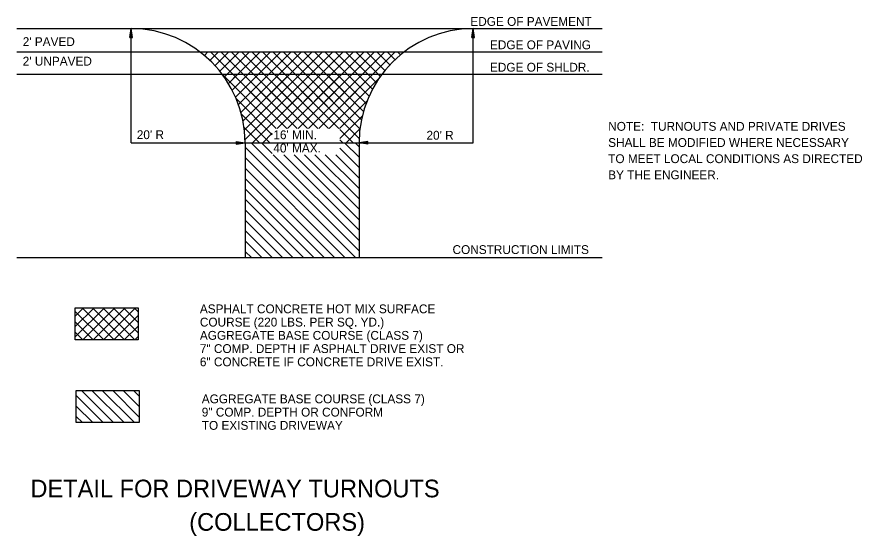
# Model space of a CAD drawing. Extents: x 836 to 5683, y -463 to 1545.
# Drawn here: x 2195 to 2769, y 147 to 499 of the extents above; entities that cross this region are included whole.
import ezdxf

# ---------------------------------------------------------------- set-up
doc = ezdxf.new("R2010")
doc.units = 0
for name, color, linetype in [('Default', 7, 'Continuous'), ('G-ANNO-NPLT', 7, 'Continuous'), ('R_Grid', 7, 'Continuous')]:
    doc.layers.add(name, color=color, linetype=linetype)

msp = doc.modelspace()

# ---------------------------------------------------------------- linework, layer by layer
at = {"layer": 'G-ANNO-NPLT'}
for p, q in [((2194.89, 491.49), (2592.63, 491.49)), ((2272.5, 414), (2272.5, 491.49)), ((2504.95, 414), (2504.95, 491.49)), ((2194.89, 475.72), (2592.63, 475.72)), ((2322.37, 473.31), (2324.78, 475.72)), ((2326.1, 469.96), (2331.85, 475.72)), ((2378.31, 423.79), (2326.38, 475.72)), ((2329.6, 466.39), (2338.92, 475.72)), ((2332.86, 462.59), (2345.99, 475.72)), ((2385.38, 423.79), (2333.45, 475.72)), ((2335.87, 458.52), (2353.06, 475.72)), ((2338.66, 454.25), (2360.14, 475.72)), ((2392.45, 423.79), (2340.52, 475.72)), ((2341.22, 449.73), (2367.21, 475.72)), ((2343.5, 444.94), (2374.28, 475.72)), ((2345.5, 439.87), (2381.35, 475.72)), ((2347.19, 434.49), (2388.42, 475.72)), ((2399.52, 423.79), (2347.59, 475.72)), ((2348.53, 428.75), (2395.49, 475.72)), ((2349.46, 422.61), (2402.56, 475.72)), ((2349.92, 416), (2409.63, 475.72)), ((2406.59, 423.79), (2354.66, 475.72)), ((2354.99, 414), (2416.7, 475.72)), ((2413.66, 423.79), (2361.74, 475.72)), ((2427.58, 416.95), (2368.81, 475.72)), ((2371.85, 423.79), (2423.77, 475.72)), ((2428.1, 423.5), (2375.88, 475.72)), ((2378.92, 423.79), (2430.85, 475.72)), ((2429.08, 429.58), (2382.95, 475.72)), ((2385.99, 423.79), (2437.92, 475.72)), ((2430.47, 435.27), (2390.02, 475.72)), ((2393.06, 423.79), (2444.99, 475.72)), ((2432.2, 440.6), (2397.09, 475.72)), ((2400.13, 423.79), (2452.06, 475.72)), ((2434.25, 445.63), (2404.16, 475.72)), ((2436.57, 450.38), (2411.23, 475.72)), ((2439.16, 454.86), (2418.3, 475.72)), ((2441.99, 459.1), (2425.37, 475.72)), ((2445.03, 463.13), (2432.45, 475.72)), ((2448.33, 466.9), (2439.52, 475.72)), ((2451.86, 470.44), (2446.59, 475.72)), ((2455.62, 473.75), (2453.66, 475.72)), ((2194.89, 460.5), (2592.63, 460.5)), ((2371.23, 423.79), (2334.37, 460.66)), ((2371.23, 423.79), (2334.53, 460.5)), ((2335.87, 458.52), (2337.84, 460.5)), ((2338.66, 454.25), (2344.91, 460.5)), ((2341.22, 449.73), (2351.99, 460.5)), ((2378.31, 423.79), (2341.6, 460.5)), ((2343.5, 444.94), (2359.06, 460.5)), ((2345.5, 439.87), (2366.13, 460.5)), ((2347.19, 434.49), (2373.2, 460.5)), ((2348.53, 428.75), (2380.27, 460.5)), ((2385.38, 423.79), (2348.67, 460.5)), ((2349.46, 422.61), (2387.34, 460.5)), ((2349.92, 416), (2394.41, 460.5)), ((2354.99, 414), (2401.48, 460.5)), ((2392.45, 423.79), (2355.74, 460.5)), ((2399.52, 423.79), (2362.81, 460.5)), ((2406.59, 423.79), (2369.88, 460.5)), ((2371.85, 423.79), (2408.55, 460.5)), ((2413.66, 423.79), (2376.96, 460.5)), ((2378.92, 423.79), (2415.62, 460.5)), ((2427.58, 416.95), (2384.03, 460.5)), ((2385.99, 423.79), (2422.7, 460.5)), ((2428.1, 423.5), (2391.1, 460.5)), ((2393.06, 423.79), (2429.77, 460.5)), ((2429.08, 429.58), (2398.17, 460.5)), ((2400.13, 423.79), (2436.84, 460.5)), ((2430.47, 435.27), (2405.24, 460.5)), ((2432.2, 440.6), (2412.31, 460.5)), ((2434.25, 445.63), (2419.38, 460.5)), ((2436.57, 450.38), (2426.45, 460.5)), ((2439.16, 454.86), (2433.52, 460.5)), ((2441.99, 459.1), (2440.6, 460.5)), ((2407.2, 423.79), (2440.79, 457.38)), ((2407.2, 423.79), (2440.79, 457.38)), ((2368.5, 419.45), (2343.85, 444.1)), ((2368.5, 419.45), (2343.85, 444.1)), ((2414.27, 423.79), (2432.91, 442.42)), ((2414.27, 423.79), (2432.91, 442.42)), ((2366.88, 414), (2347.46, 433.42)), ((2366.88, 414), (2347.46, 433.42)), ((2414.35, 416.8), (2429.65, 432.1)), ((2414.35, 416.8), (2429.65, 432.1)), ((2359.81, 414), (2349.25, 424.56)), ((2359.81, 414), (2349.25, 424.56)), ((2362.06, 414), (2368.5, 420.44)), ((2362.06, 414), (2368.5, 420.44)), ((2423.45, 414), (2414.35, 423.1)), ((2423.45, 414), (2414.35, 423.1)), ((2418.63, 414), (2428.09, 423.47)), ((2418.63, 414), (2428.09, 423.47)), ((2272.5, 414), (2349.99, 414)), ((2349.99, 414), (2349.99, 336.01)), ((2349.99, 414), (2427.47, 414)), ((2427.47, 340.56), (2354.03, 414)), ((2368.5, 406.61), (2361.1, 414)), ((2368.5, 413.68), (2368.17, 414)), ((2368.5, 413.68), (2368.17, 414)), ((2416.38, 414), (2414.35, 416.03)), ((2416.38, 414), (2414.35, 416.03)), ((2427.47, 404.2), (2417.67, 414)), ((2427.47, 411.28), (2424.74, 414)), ((2427.47, 411.28), (2424.74, 414)), ((2427.47, 414), (2427.47, 336.01)), ((2427.47, 414), (2504.95, 414)), ((2424.96, 336.01), (2349.99, 410.98)), ((2427.47, 397.13), (2414.35, 410.25)), ((2417.89, 336.01), (2349.99, 403.91)), ((2427.47, 347.64), (2369.18, 405.92)), ((2427.47, 354.71), (2376.25, 405.92)), ((2427.47, 361.78), (2383.33, 405.92)), ((2427.47, 368.85), (2390.4, 405.92)), ((2427.47, 375.92), (2397.47, 405.92)), ((2427.47, 382.99), (2404.54, 405.92)), ((2427.47, 390.06), (2411.61, 405.92)), ((2410.82, 336.01), (2349.99, 396.84)), ((2403.75, 336.01), (2349.99, 389.76)), ((2396.67, 336.01), (2349.99, 382.69)), ((2389.6, 336.01), (2349.99, 375.62)), ((2382.53, 336.01), (2349.99, 368.55)), ((2375.46, 336.01), (2349.99, 361.48)), ((2368.39, 336.01), (2349.99, 354.41)), ((2361.32, 336.01), (2349.99, 347.34)), ((2354.25, 336.01), (2349.99, 340.27)), ((2194.89, 336.01), (2592.63, 336.01)), ((2234.54, 296.26), (2240.23, 301.95)), ((2234.54, 289.19), (2247.3, 301.95)), ((2234.54, 282.12), (2254.37, 301.95)), ((2253.9, 280.13), (2234.54, 299.5)), ((2260.97, 280.13), (2239.15, 301.95)), ((2239.62, 280.13), (2261.44, 301.95)), ((2268.04, 280.13), (2246.22, 301.95)), ((2246.69, 280.13), (2268.51, 301.95)), ((2275.11, 280.13), (2253.29, 301.95)), ((2253.76, 280.13), (2275.59, 301.95)), ((2277.35, 284.97), (2260.36, 301.95)), ((2277.35, 292.04), (2267.43, 301.95)), ((2277.35, 299.11), (2274.5, 301.95)), ((2260.84, 280.13), (2277.35, 296.64)), ((2246.83, 280.13), (2234.54, 292.42)), ((2267.91, 280.13), (2277.35, 289.57)), ((2239.76, 280.13), (2234.54, 285.35)), ((2274.98, 280.13), (2277.35, 282.5)), ((2253.57, 223.98), (2235.22, 242.33)), ((2260.64, 223.98), (2238.82, 245.8)), ((2267.71, 223.98), (2245.89, 245.8)), ((2274.78, 223.98), (2252.96, 245.8)), ((2278.03, 227.8), (2260.03, 245.8)), ((2278.03, 234.87), (2267.11, 245.8)), ((2278.03, 241.94), (2274.18, 245.8)), ((2246.5, 223.98), (2235.22, 235.25)), ((2239.43, 223.98), (2235.22, 228.18))]:
    msp.add_line(p, q, dxfattribs=at)
for points in [[(2234.54, 301.95), (2277.35, 301.95), (2277.35, 280.13), (2234.54, 280.13)], [(2235.22, 245.8), (2278.03, 245.8), (2278.03, 223.98), (2235.22, 223.98)]]:
    msp.add_lwpolyline(points, close=True, dxfattribs=at)
for centre, start, end in [((2272.5, 414), 0, 90), ((2504.95, 414), 90, 180)]:
    msp.add_arc(centre, 77.48, start, end, dxfattribs=at)
at = {"layer": 'R_Grid'}
for p, q in [((2271.6, 485.49), (2272.5, 491.49)), ((2271.6, 485.49), (2272.5, 491.49)), ((2271.75, 485.49), (2272.5, 490.49)), ((2271.75, 485.49), (2272.5, 490.49)), ((2271.91, 485.49), (2272.5, 489.45)), ((2271.91, 485.49), (2272.5, 489.45)), ((2272.06, 485.49), (2272.5, 488.46)), ((2272.06, 485.49), (2272.5, 488.46)), ((2273.4, 485.49), (2272.5, 491.49)), ((2273.4, 485.49), (2272.5, 491.49)), ((2273.25, 485.49), (2272.5, 490.49)), ((2273.25, 485.49), (2272.5, 490.49)), ((2273.1, 485.49), (2272.5, 489.45)), ((2273.1, 485.49), (2272.5, 489.45)), ((2272.95, 485.49), (2272.5, 488.46)), ((2272.95, 485.49), (2272.5, 488.46)), ((2504.05, 485.49), (2504.95, 491.49)), ((2504.05, 485.49), (2504.95, 491.49)), ((2504.2, 485.49), (2504.95, 490.49)), ((2504.2, 485.49), (2504.95, 490.49)), ((2504.36, 485.49), (2504.95, 489.45)), ((2504.36, 485.49), (2504.95, 489.45)), ((2504.51, 485.49), (2504.95, 488.46)), ((2504.51, 485.49), (2504.95, 488.46)), ((2505.85, 485.49), (2504.95, 491.49)), ((2505.85, 485.49), (2504.95, 491.49)), ((2505.7, 485.49), (2504.95, 490.49)), ((2505.7, 485.49), (2504.95, 490.49)), ((2505.55, 485.49), (2504.95, 489.45)), ((2505.55, 485.49), (2504.95, 489.45)), ((2505.4, 485.49), (2504.95, 488.46)), ((2505.4, 485.49), (2504.95, 488.46)), ((2271.6, 485.49), (2273.4, 485.49)), ((2271.6, 485.49), (2273.4, 485.49)), ((2272.21, 485.49), (2272.5, 487.44)), ((2272.21, 485.49), (2272.5, 487.44)), ((2272.36, 485.49), (2272.5, 486.44)), ((2272.36, 485.49), (2272.5, 486.44)), ((2272.8, 485.49), (2272.5, 487.44)), ((2272.8, 485.49), (2272.5, 487.44)), ((2272.64, 485.49), (2272.5, 486.44)), ((2272.64, 485.49), (2272.5, 486.44)), ((2504.05, 485.49), (2505.85, 485.49)), ((2504.05, 485.49), (2505.85, 485.49)), ((2504.66, 485.49), (2504.95, 487.44)), ((2504.66, 485.49), (2504.95, 487.44)), ((2504.81, 485.49), (2504.95, 486.44)), ((2504.81, 485.49), (2504.95, 486.44)), ((2505.25, 485.49), (2504.95, 487.44)), ((2505.25, 485.49), (2504.95, 487.44)), ((2505.1, 485.49), (2504.95, 486.44)), ((2505.1, 485.49), (2504.95, 486.44)), ((2343.99, 414.9), (2349.99, 414)), ((2343.99, 414.9), (2343.99, 413.1)), ((2343.99, 414.9), (2349.99, 414)), ((2343.99, 414.9), (2343.99, 413.1)), ((2343.99, 414.9), (2349.99, 414)), ((2343.99, 414.9), (2343.99, 413.1)), ((2343.99, 414.75), (2348.98, 414)), ((2343.99, 414.75), (2348.98, 414)), ((2343.99, 414.75), (2348.98, 414)), ((2343.99, 414.6), (2347.95, 414)), ((2343.99, 414.6), (2347.95, 414)), ((2343.99, 414.6), (2347.95, 414)), ((2343.99, 414.45), (2346.95, 414)), ((2343.99, 414.45), (2346.95, 414)), ((2343.99, 414.45), (2346.95, 414)), ((2343.99, 414.3), (2345.94, 414)), ((2343.99, 414.3), (2345.94, 414)), ((2343.99, 414.3), (2345.94, 414)), ((2343.99, 414.15), (2344.93, 414)), ((2343.99, 414.15), (2344.93, 414)), ((2343.99, 414.15), (2344.93, 414)), ((2343.99, 413.1), (2349.99, 414)), ((2343.99, 413.71), (2345.94, 414)), ((2343.99, 413.41), (2347.95, 414)), ((2343.99, 413.25), (2348.98, 414)), ((2343.99, 413.56), (2346.95, 414)), ((2343.99, 413.86), (2344.93, 414)), ((2343.99, 413.1), (2349.99, 414)), ((2343.99, 413.71), (2345.94, 414)), ((2343.99, 413.41), (2347.95, 414)), ((2343.99, 413.25), (2348.98, 414)), ((2343.99, 413.56), (2346.95, 414)), ((2343.99, 413.86), (2344.93, 414)), ((2343.99, 413.1), (2349.99, 414)), ((2343.99, 413.71), (2345.94, 414)), ((2343.99, 413.41), (2347.95, 414)), ((2343.99, 413.25), (2348.98, 414)), ((2343.99, 413.56), (2346.95, 414)), ((2343.99, 413.86), (2344.93, 414)), ((2433.47, 414.9), (2427.47, 414)), ((2433.47, 414.9), (2427.47, 414)), ((2433.47, 414.9), (2427.47, 414)), ((2433.47, 413.1), (2427.47, 414)), ((2433.47, 413.1), (2427.47, 414)), ((2433.47, 413.1), (2427.47, 414)), ((2433.47, 414.75), (2428.47, 414)), ((2433.47, 414.75), (2428.47, 414)), ((2433.47, 414.75), (2428.47, 414)), ((2433.47, 413.25), (2428.47, 414)), ((2433.47, 413.25), (2428.47, 414)), ((2433.47, 413.25), (2428.47, 414)), ((2433.47, 414.6), (2429.5, 414)), ((2433.47, 414.6), (2429.5, 414)), ((2433.47, 414.6), (2429.5, 414)), ((2433.47, 413.41), (2429.5, 414)), ((2433.47, 413.41), (2429.5, 414)), ((2433.47, 413.41), (2429.5, 414)), ((2433.47, 414.45), (2430.5, 414)), ((2433.47, 414.45), (2430.5, 414)), ((2433.47, 414.45), (2430.5, 414)), ((2433.47, 413.56), (2430.5, 414)), ((2433.47, 413.56), (2430.5, 414)), ((2433.47, 413.56), (2430.5, 414)), ((2433.47, 414.3), (2431.52, 414)), ((2433.47, 414.3), (2431.52, 414)), ((2433.47, 414.3), (2431.52, 414)), ((2433.47, 413.71), (2431.52, 414)), ((2433.47, 413.71), (2431.52, 414)), ((2433.47, 413.71), (2431.52, 414)), ((2433.47, 414.15), (2432.52, 414)), ((2433.47, 414.15), (2432.52, 414)), ((2433.47, 414.15), (2432.52, 414)), ((2433.47, 413.86), (2432.52, 414)), ((2433.47, 413.86), (2432.52, 414)), ((2433.47, 413.86), (2432.52, 414)), ((2433.47, 413.1), (2433.47, 414.9)), ((2433.47, 413.1), (2433.47, 414.9)), ((2433.47, 413.1), (2433.47, 414.9))]:
    msp.add_line(p, q, dxfattribs=at)

# ---------------------------------------------------------------- texts
at = {"layer": 'Default'}
for s, p in [('NOTE:  TURNOUTS AND PRIVATE DRIVES', (2596.82, 422.14)), ('SHALL BE MODIFIED WHERE NECESSARY', (2596.82, 411.16)), ('TO MEET LOCAL CONDITIONS AS DIRECTED', (2596.82, 400.19)), ('BY THE ENGINEER.', (2596.82, 389.21))]:
    msp.add_text(s, height=6, dxfattribs=at).set_placement(p)
at = {"layer": 'G-ANNO-NPLT'}
for s, height, p in [('EDGE OF PAVEMENT', 6, (2503.14, 493.36)), ("2' PAVED", 6, (2198.85, 479.66)), ('EDGE OF PAVING', 6, (2516.45, 477.5)), ("2' UNPAVED", 6, (2198.85, 466.41)), ('EDGE OF SHLDR.', 6, (2516.45, 462.28)), ("20' R", 6, (2276.38, 416.48)), ("16' MIN.", 6, (2369.22, 416.41)), ("20' R", 6, (2473.29, 416.1)), ("40' MAX.", 6, (2369.22, 407.41)), ('CONSTRUCTION LIMITS', 6, (2491.01, 338.45)), ('ASPHALT CONCRETE HOT MIX SURFACE', 6, (2319.27, 298.23)), ('COURSE (220 LBS. PER SQ. YD.) ', 6, (2319.27, 289.23)), ('AGGREGATE BASE COURSE (CLASS 7) ', 6, (2319.27, 280.23)), ('7" COMP. DEPTH IF ASPHALT DRIVE EXIST OR', 6, (2319.27, 271.23)), ('6" CONCRETE IF CONCRETE DRIVE EXIST.', 6, (2319.27, 262.23)), ('AGGREGATE BASE COURSE (CLASS 7)', 6, (2320.56, 237.11)), ('9" COMP. DEPTH OR CONFORM', 6, (2320.56, 228.11)), ('TO EXISTING DRIVEWAY', 6, (2320.56, 219.11)), ('DETAIL FOR DRIVEWAY TURNOUTS', 12, (2204.07, 173.25)), ('(COLLECTORS)', 12, (2312.02, 150.56))]:
    msp.add_text(s, height=height, dxfattribs=at).set_placement(p)

doc.saveas('drawing.dxf')
